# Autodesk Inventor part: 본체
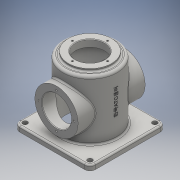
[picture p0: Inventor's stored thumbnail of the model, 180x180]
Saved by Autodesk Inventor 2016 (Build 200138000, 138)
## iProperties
Created: 2019-08
Part Number: 본체
Material: 일반
Document SubType Name: Modeling
Designer: user
Density: 1 g/cm^3
Appearance: 기본값
Author: user
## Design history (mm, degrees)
sketch "스케치1"
  geometry: L1 (-70, 70)-(70, 70); L2 (70, 70)-(70, -70); L3 (70, -70)-(-70, -70); L4 (-70, -70)-(-70, 70); L5 (-70, 70)-(70, -70); L6 (70, 70)-(-70, -70); 1 further point
  constraints: 12 end point, 2 midpoint, 2 parallel, 1 horizontal, 1 perpendicular
  dimensions: "d0" = 140 distance of L2.end L3.end; "d1" = 140 distance of L1.end L2.end
extrude "돌출1" new body sketch "스케치1" distance "d2" = 10; taper "d3" = 0 deg
sketch "스케치2"
  geometry: C1 r 50 at (0, 0); 1 further point
  constraints: 1 centre point, 1 coincident
  dimensions: "d4" = 100 diameter of C1
extrude "돌출2" join sketch "스케치2" distance "d5" = 110; taper "d6" = 0 deg
sketch "스케치5"
  geometry: C1 r 45 at (0, 0); 1 further point
  constraints: 1 centre point, 1 coincident
  dimensions: "d15" = 90 diameter of C1
extrude "돌출4" cut sketch "스케치5" distance "d16" = 112; taper "d17" = 0 deg
node "작업 평면3"
sketch "스케치6"
  geometry: L1 (-70, 0)-(70, 0) reference; C1 r 40 at (0, 60); 3 further points
  constraints: 2 midpoint, 1 centre point, 1 vertical alignment
  dimensions: "d20" = 80 diameter of C1; "d21" = 60 distance from line of C1.centre L1
extrude "돌출5" join sketch "스케치6" stored distance "d22" = 112; taper "d23" = 0 deg
hole "구멍1" diameter "d26" = 54; stored, may be unused: countersink angle "d30" = 90 deg, drill point angle "d32" = 118 deg; dims "d24" = 10, "d25" = 10, "d27" = 6, "d28" = 4, "d29" = 2, "d31" = 8
sketch "스케치9"
  geometry: L1 (70, -60)-(-70, -60) reference; 3 further points
  constraints: 1 midpoint, 1 vertical alignment
  dimensions: "d35" = 92.5 distance from line of L1 point (0, 32.5)
hole "구멍2" sketch "스케치9" at (0, 32.5) diameter "d36" = 3.242; stored, may be unused: countersink angle "d40" = 90 deg, drill point angle "d42" = 118 deg; dims "d37" = 8, "d38" = 4, "d39" = 2, "d41" = 10
sketch "스케치10"
  geometry: C1 r 40 at (0, 0); 1 further point
  constraints: 1 centre point, 1 coincident
  dimensions: "d46" = 80 diameter of C1
extrude "돌출6" join sketch "스케치10" distance "d47" = 5; taper "d48" = 0 deg
hole "구멍3" diameter "d51" = 54; stored, may be unused: countersink angle "d55" = 90 deg, drill point angle "d57" = 118 deg; dims "d49" = 10, "d50" = 10, "d52" = 8, "d53" = 4, "d54" = 2, "d56" = 13
sketch "스케치11"
  geometry: 2 further points
  constraints: 1 vertical alignment
  dimensions: "d58" = 32.5 distance of point (0, 0) point (0, 32.5)
hole "구멍4" sketch "스케치11" at (0, 32.5) diameter "d59" = 3.242; stored, may be unused: countersink angle "d63" = 90 deg, drill point angle "d65" = 118 deg; dims "d60" = 8, "d61" = 4, "d62" = 2, "d64" = 10
fillet "모깎기1" dims "d69" = 10
hole "구멍5" diameter "d72" = 9; stored, may be unused: countersink angle "d76" = 90 deg, drill point angle "d78" = 0 deg; dims "d70" = 10, "d71" = 10, "d73" = 8, "d74" = 4, "d75" = 2, "d77" = 10
fillet "모깎기2" dims "d85" = 5
fillet "모깎기3" dims "d86" = 3
fillet "모깎기4" dims "d87" = 3
chamfer "모따기1" distance "d88" = 1; stored, may be unused: second distance "d89" = 2, angle "d90" = 45 deg
fillet "모깎기5" dims "d91" = 3
fillet "모깎기6" dims "d92" = 3
node "작업 평면4"
sketch "스케치12" dims "d0" = 140, "d1" = 140
  geometry: L1 (60, 0)-(-60, 0) reference; 2 further points
  constraints: 1 other
  dimensions: "d94" = 70 distance from line of L1 point (-2.161, 70)
feature "엠보싱1" sketch "스케치12" dims "d0" = 140, "d1" = 140, "d95" = 0.5, "d96" = 0
chamfer "모따기2" distance "d97" = 1; stored, may be unused: second distance "d98" = 2, angle "d99" = 45 deg
node "솔리드1"
mirror "대칭1"
pattern_circular "원형 패턴1" dims angle "d44" = 360 deg
mirror "대칭2"
pattern_circular "원형 패턴2" dims angle "d67" = 360 deg
pattern_linear "직사각형 패턴1" dims "d81" = 120
other parameters: "d18" = -62
